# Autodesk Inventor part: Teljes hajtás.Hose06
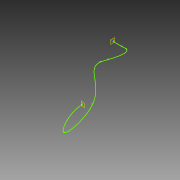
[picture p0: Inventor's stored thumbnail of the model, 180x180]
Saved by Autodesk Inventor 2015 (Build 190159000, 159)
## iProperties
_PSKETCH_SNAP: False
_PSKETCH_RSNP: False
_BASENETWORK_NOTAUTODIMENSION: False
StyleName: _Piping Style 20
Created: 2013-02
Part Number: Teljes hajtás.Hose06
Material: Generic
Document SubType Name: Modeling
Designer: Marci
Density: 1 g/cm^3
Appearance: Default
ActiveState: True
Angle: UnInitValue
BendRadius: 0.500 in
CouplingKey: UnInitValue
DefaultBendRadius: UnInitValue
Diameter: 1/4
DiameterType: Nominal
Elbow45Key: UnInitValue
Elbow90Key: UnInitValue
ElbowCustomKey: UnInitValue
Ending: UnInitValue
FittingMaterial: UnInitValue
FittingStandard: UnInitValue
FlangeKey: UnInitValue
Gap: UnInitValue
GasketKey: UnInitValue
ID: 0,635
IsButtWelded: UnInitValue
IsFlanged: UnInitValue
IsSelfDraining: UnInitValue
Material: UnInitValue
MixedUnits: UnInitValue
Name: Hydraulic Hose - No Fittings
OD: 1,4986
PipeKey: v3#d489867e-ac9b-47ea-b952-0a1b885f66be#1
PipeType: Flexible Hose
PipingComponentColor: Blue - Wall Paint - Glossy
RoundUpValue: 0.125 in
RouteDirection45: UnInitValue
RouteDirection90: UnInitValue
Schedule: ID=0.25
ShowGap: UnInitValue
Standard: UnInitValue
SuppressEndFitting: True
SuppressStartFitting: True
UseFlangsForCouplings: UnInitValue
UseSubASM: True
_ComponentInfo: <CS><C N="Pipe" R="0,749300" OR="0,749300" IR="0,317500" PL="PL" PartType="pipe" SymKey="" PN="Parker hidraulikatömlő - No Skive 1/4"><CO N="1"><FE V="0"/><FD V
Author: Marci
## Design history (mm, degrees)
workpoint "Work Point1"
workplane "Work Plane1"
workpoint "Work Point2"
workplane "Work Plane2"
sketch "3D Sketch1" dims "d0" = 10, "d1" = 0.1 (derived), "d2" = 10, "d3" = 0.1 (derived)
other parameters: "B" = 12.7 [user parameter]
